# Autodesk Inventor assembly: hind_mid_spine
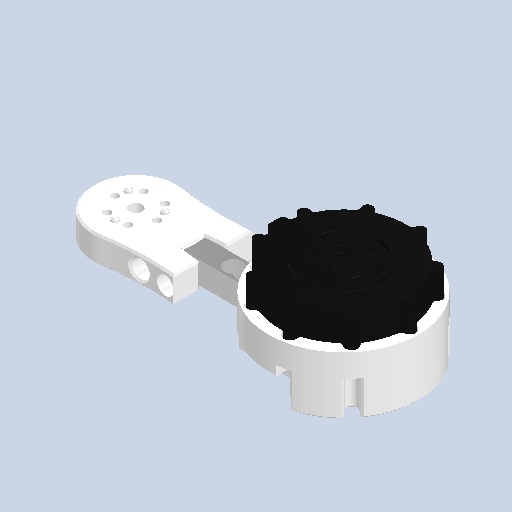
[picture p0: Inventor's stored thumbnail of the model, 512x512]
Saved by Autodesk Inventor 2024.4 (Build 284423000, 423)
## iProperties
Created: 2026-01
Part Number: hind_mid_spine
Document SubType Name: Assembly
Designer: AdminForWorker
Title: hind_mid_spine v1
Author: AdminForWorker
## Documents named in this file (4)
- c:\worker\convert-fusion-r06-cosv3\tmp\job-1\21\temp\files\7a09565c-e9bc-4d1e-b766-0c54150a3d25\bb0950ef-d413-479e-b58c-a1aa4eddb0ac.iam
- c:\worker\convert-fusion-r06-cosv3\tmp\job-1\21\temp\files\7a09565c-e9bc-4d1e-b766-0c54150a3d25\CyberGear.ipt
- c:\worker\convert-fusion-r06-cosv3\tmp\job-1\21\temp\files\7a09565c-e9bc-4d1e-b766-0c54150a3d25\load_cell.ipt
- c:\worker\convert-fusion-r06-cosv3\tmp\job-1\21\temp\files\7a09565c-e9bc-4d1e-b766-0c54150a3d25\Xiaomi_spine1-1.ipt
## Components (3 placed, 3 different names)
1. CyberGear:1
2. load_cell:1
3. Xiaomi_spine1-1:1
